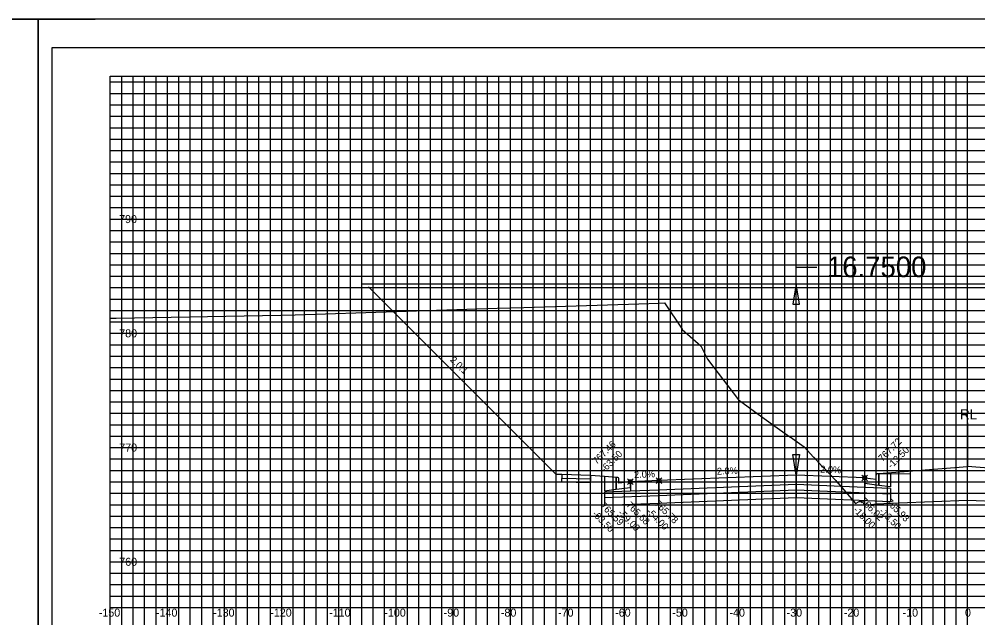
# Model space of a CAD drawing. Extents: x 578243 to 601557, y 174899 to 175559.
# Drawn here: x 600533.9 to 600701.6, y 175014 to 175118.8 of the extents above; entities that cross this region are included whole.
import ezdxf

# ---------------------------------------------------------------- set-up
doc = ezdxf.new("R2010")
doc.units = 0
for name, color, linetype in [('E_PROF_Grid', 7, 'Continuous'), ('E_PROF_GridMin', 7, 'Continuous'), ('P_CRDR_Label', 7, 'Continuous'), ('P_CRDR_Link', 7, 'Continuous'), ('P_E_XS_Ground', 7, 'Continuous'), ('P_RW_SlopeIntercepts', 7, 'Continuous'), ('P_XS_Text', 7, 'Continuous'), ('PLT_Sheet_Border', 7, 'Continuous'), ('PLT_Sheet_Info', 7, 'Continuous')]:
    doc.layers.add(name, color=color, linetype=linetype)

msp = doc.modelspace()

# ---------------------------------------------------------------- linework, layer by layer
at = {"layer": 'E_PROF_Grid'}
for p, q in [((600559.84, 174913.8), (600559.84, 175108.8)), ((600569.84, 174913.8), (600569.84, 175108.8)), ((600579.84, 174913.8), (600579.84, 175108.8)), ((600589.84, 174913.8), (600589.84, 175108.8)), ((600599.84, 174913.8), (600599.84, 175108.8)), ((600609.84, 174913.8), (600609.84, 175108.8)), ((600619.84, 174913.8), (600619.84, 175108.8)), ((600629.84, 174913.8), (600629.84, 175108.8)), ((600639.84, 174913.8), (600639.84, 175108.8)), ((600649.84, 174913.8), (600649.84, 175108.8)), ((600659.84, 174913.8), (600659.84, 175108.8)), ((600669.84, 174913.8), (600669.84, 175108.8)), ((600679.84, 174913.8), (600679.84, 175108.8)), ((600689.84, 174913.8), (600689.84, 175108.8)), ((600699.84, 174913.8), (600699.84, 175108.8)), ((600549.84, 175103.8), (600864.84, 175103.8)), ((600549.84, 175093.8), (600864.84, 175093.8)), ((600549.84, 175083.8), (600864.84, 175083.8)), ((600549.84, 175073.8), (600864.84, 175073.8)), ((600549.84, 175063.8), (600864.84, 175063.8)), ((600549.84, 175053.8), (600864.84, 175053.8)), ((600549.84, 175043.8), (600864.84, 175043.8)), ((600549.84, 175033.8), (600864.84, 175033.8)), ((600549.84, 175023.8), (600864.84, 175023.8))]:
    msp.add_line(p, q, dxfattribs=at)
at = {"layer": 'E_PROF_GridMin'}
for p, q in [((600551.84, 174913.8), (600551.84, 175108.8)), ((600553.84, 174913.8), (600553.84, 175108.8)), ((600555.84, 174913.8), (600555.84, 175108.8)), ((600557.84, 174913.8), (600557.84, 175108.8)), ((600561.84, 174913.8), (600561.84, 175108.8)), ((600563.84, 174913.8), (600563.84, 175108.8)), ((600565.84, 174913.8), (600565.84, 175108.8)), ((600567.84, 174913.8), (600567.84, 175108.8)), ((600571.84, 174913.8), (600571.84, 175108.8)), ((600573.84, 174913.8), (600573.84, 175108.8)), ((600575.84, 174913.8), (600575.84, 175108.8)), ((600577.84, 174913.8), (600577.84, 175108.8)), ((600581.84, 174913.8), (600581.84, 175108.8)), ((600583.84, 174913.8), (600583.84, 175108.8)), ((600585.84, 174913.8), (600585.84, 175108.8)), ((600587.84, 174913.8), (600587.84, 175108.8)), ((600591.84, 174913.8), (600591.84, 175108.8)), ((600593.84, 174913.8), (600593.84, 175108.8)), ((600595.84, 174913.8), (600595.84, 175108.8)), ((600597.84, 174913.8), (600597.84, 175108.8)), ((600601.84, 174913.8), (600601.84, 175108.8)), ((600603.84, 174913.8), (600603.84, 175108.8)), ((600605.84, 174913.8), (600605.84, 175108.8)), ((600607.84, 174913.8), (600607.84, 175108.8)), ((600611.84, 174913.8), (600611.84, 175108.8)), ((600613.84, 174913.8), (600613.84, 175108.8)), ((600615.84, 174913.8), (600615.84, 175108.8)), ((600617.84, 174913.8), (600617.84, 175108.8)), ((600621.84, 174913.8), (600621.84, 175108.8)), ((600623.84, 174913.8), (600623.84, 175108.8)), ((600625.84, 174913.8), (600625.84, 175108.8)), ((600627.84, 174913.8), (600627.84, 175108.8)), ((600631.84, 174913.8), (600631.84, 175108.8)), ((600633.84, 174913.8), (600633.84, 175108.8)), ((600635.84, 174913.8), (600635.84, 175108.8)), ((600637.84, 174913.8), (600637.84, 175108.8)), ((600641.84, 174913.8), (600641.84, 175108.8)), ((600643.84, 174913.8), (600643.84, 175108.8)), ((600645.84, 174913.8), (600645.84, 175108.8)), ((600647.84, 174913.8), (600647.84, 175108.8)), ((600651.84, 174913.8), (600651.84, 175108.8)), ((600653.84, 174913.8), (600653.84, 175108.8)), ((600655.84, 174913.8), (600655.84, 175108.8)), ((600657.84, 174913.8), (600657.84, 175108.8)), ((600661.84, 174913.8), (600661.84, 175108.8)), ((600663.84, 174913.8), (600663.84, 175108.8)), ((600665.84, 174913.8), (600665.84, 175108.8)), ((600667.84, 174913.8), (600667.84, 175108.8)), ((600671.84, 174913.8), (600671.84, 175108.8)), ((600673.84, 174913.8), (600673.84, 175108.8)), ((600675.84, 174913.8), (600675.84, 175108.8)), ((600677.84, 174913.8), (600677.84, 175108.8)), ((600681.84, 174913.8), (600681.84, 175108.8)), ((600683.84, 174913.8), (600683.84, 175108.8)), ((600685.84, 174913.8), (600685.84, 175108.8)), ((600687.84, 174913.8), (600687.84, 175108.8)), ((600691.84, 174913.8), (600691.84, 175108.8)), ((600693.84, 174913.8), (600693.84, 175108.8)), ((600695.84, 174913.8), (600695.84, 175108.8)), ((600697.84, 174913.8), (600697.84, 175108.8)), ((600549.84, 175107.8), (600864.84, 175107.8)), ((600549.84, 175105.8), (600864.84, 175105.8)), ((600549.84, 175101.8), (600864.84, 175101.8)), ((600549.84, 175099.8), (600864.84, 175099.8)), ((600549.84, 175097.8), (600864.84, 175097.8)), ((600549.84, 175095.8), (600864.84, 175095.8)), ((600549.84, 175091.8), (600864.84, 175091.8)), ((600549.84, 175089.8), (600864.84, 175089.8)), ((600549.84, 175087.8), (600864.84, 175087.8)), ((600549.84, 175085.8), (600864.84, 175085.8)), ((600549.84, 175081.8), (600864.84, 175081.8)), ((600549.84, 175079.8), (600864.84, 175079.8)), ((600549.84, 175077.8), (600864.84, 175077.8)), ((600549.84, 175075.8), (600864.84, 175075.8)), ((600549.84, 175071.8), (600864.84, 175071.8)), ((600549.84, 175069.8), (600864.84, 175069.8)), ((600549.84, 175067.8), (600864.84, 175067.8)), ((600549.84, 175065.8), (600864.84, 175065.8)), ((600549.84, 175061.8), (600864.84, 175061.8)), ((600549.84, 175059.8), (600864.84, 175059.8)), ((600549.84, 175057.8), (600864.84, 175057.8)), ((600549.84, 175055.8), (600864.84, 175055.8)), ((600549.84, 175051.8), (600864.84, 175051.8)), ((600549.84, 175049.8), (600864.84, 175049.8)), ((600549.84, 175047.8), (600864.84, 175047.8)), ((600549.84, 175045.8), (600864.84, 175045.8)), ((600549.84, 175041.8), (600864.84, 175041.8)), ((600549.84, 175039.8), (600864.84, 175039.8)), ((600549.84, 175037.8), (600864.84, 175037.8)), ((600549.84, 175035.8), (600864.84, 175035.8)), ((600549.84, 175031.8), (600864.84, 175031.8)), ((600549.84, 175029.8), (600864.84, 175029.8)), ((600549.84, 175027.8), (600864.84, 175027.8)), ((600549.84, 175025.8), (600864.84, 175025.8)), ((600549.84, 175021.8), (600864.84, 175021.8)), ((600549.84, 175019.8), (600864.84, 175019.8)), ((600549.84, 175017.8), (600864.84, 175017.8)), ((600549.84, 175015.8), (600864.84, 175015.8))]:
    msp.add_line(p, q, dxfattribs=at)
at = {"layer": 'P_CRDR_Label'}
for points in [[(600699.84, 175048.11), (600699.84, 175040.49)], [(600640.35, 175037.32), (600641.34, 175038.31)], [(600640.35, 175038.31), (600641.34, 175037.32)], [(600645.35, 175037.52), (600646.34, 175038.51)], [(600645.35, 175038.51), (600646.34, 175037.52)], [(600681.35, 175038), (600682.34, 175038.99)], [(600681.35, 175038.99), (600682.34, 175038)]]:
    msp.add_lwpolyline(points, dxfattribs=at)
for centre in [(600640.84, 175037.82), (600645.84, 175038.02), (600681.84, 175038.5)]:
    msp.add_circle(centre, 0.35, dxfattribs=at)
at = {"layer": 'P_CRDR_Link'}
msp.add_line((600594.99, 175071.96), (600627.84, 175039.11), dxfattribs=at)
for points in [[(600684.34, 175039.25), (600699.84, 175040.49)], [(600684.34, 175039.25), (600699.84, 175040.49)], [(600715.34, 175039.25), (600699.84, 175040.49)], [(600715.34, 175039.25), (600699.84, 175040.49)], [(600628.84, 175039.08), (600627.84, 175039.11)], [(600628.84, 175039.08), (600627.84, 175039.11)], [(600633.84, 175038.93), (600628.84, 175039.08)], [(600633.84, 175038.93), (600628.84, 175039.08)], [(600628.84, 175039.08), (600628.85, 175038.41)], [(600633.84, 175038.26), (600628.85, 175038.41)], [(600628.85, 175037.75), (600628.85, 175038.41)], [(600633.83, 175037.6), (600628.85, 175037.75)], [(600633.84, 175038.26), (600633.83, 175037.6)], [(600636.34, 175038.73), (600633.84, 175038.93)], [(600636.34, 175038.73), (600633.84, 175038.93)], [(600633.84, 175038.93), (600633.84, 175038.26)], [(600638.34, 175038.57), (600636.34, 175038.73)], [(600636.34, 175038.73), (600636.34, 175036.25)], [(600636.34, 175038.73), (600636.34, 175036.25)], [(600636.34, 175038.73), (600636.34, 175036.25)], [(600638.66, 175038.57), (600638.34, 175038.57)], [(600638.66, 175038.57), (600638.34, 175038.57)], [(600638.34, 175038.57), (600638.34, 175036.5)], [(600638.34, 175036.5), (600638.34, 175038.57)], [(600638.74, 175038.52), (600638.66, 175038.57)], [(600638.74, 175038.52), (600638.66, 175038.57)], [(600638.8, 175038.41), (600638.74, 175038.52)], [(600638.8, 175038.41), (600638.74, 175038.52)], [(600638.83, 175038.25), (600638.8, 175038.41)], [(600638.83, 175038.25), (600638.8, 175038.41)], [(600638.84, 175037.57), (600638.83, 175038.25)], [(600638.84, 175037.57), (600638.83, 175038.25)], [(600640.84, 175037.82), (600638.84, 175037.57)], [(600640.84, 175037.82), (600638.84, 175037.57)], [(600645.84, 175038.02), (600640.84, 175037.82)], [(600640.84, 175037.82), (600640.84, 175036.15)], [(600640.84, 175036.82), (600640.84, 175037.82)], [(600669.84, 175038.98), (600645.84, 175038.02)], [(600645.84, 175038.02), (600645.84, 175036.35)], [(600645.84, 175038.02), (600645.84, 175036.35)], [(600681.84, 175038.5), (600669.84, 175038.98)], [(600669.84, 175038.98), (600669.84, 175037.31)], [(600669.84, 175038.98), (600669.84, 175037.31)], [(600681.84, 175038.5), (600683.84, 175038.25)], [(600681.84, 175038.5), (600683.84, 175038.25)], [(600681.84, 175037.5), (600681.84, 175038.5)], [(600681.84, 175038.5), (600681.84, 175036.83)], [(600683.84, 175038.25), (600683.85, 175038.93)], [(600683.84, 175038.25), (600683.85, 175038.93)], [(600683.85, 175038.93), (600683.88, 175039.09)], [(600683.85, 175038.93), (600683.88, 175039.09)], [(600683.88, 175039.09), (600683.94, 175039.2)], [(600683.88, 175039.09), (600683.94, 175039.2)], [(600683.94, 175039.2), (600684.02, 175039.25)], [(600683.94, 175039.2), (600684.02, 175039.25)], [(600684.02, 175039.25), (600684.34, 175039.25)], [(600684.02, 175039.25), (600684.34, 175039.25)], [(600684.34, 175039.25), (600684.34, 175037.18)], [(600684.34, 175039.25), (600686.34, 175039.23)], [(600684.34, 175037.18), (600684.34, 175039.25)], [(600686.34, 175039.23), (600686.34, 175036.93)], [(600686.34, 175039.23), (600686.34, 175036.93)], [(600686.34, 175039.23), (600686.34, 175036.93)], [(600686.34, 175039.23), (600689.84, 175039.2)], [(600686.34, 175039.23), (600689.84, 175039.2)], [(600636.34, 175036.25), (600638.34, 175036.5)], [(600640.84, 175036.15), (600636.34, 175035.97)], [(600638.34, 175036.5), (600640.84, 175036.82)], [(600638.34, 175036.5), (600640.84, 175036.82)], [(600645.84, 175036.35), (600640.84, 175036.15)], [(600669.84, 175037.31), (600645.84, 175036.35)], [(600645.84, 175036.35), (600645.84, 175035.35)], [(600645.84, 175036.35), (600645.84, 175035.35)], [(600669.84, 175036.31), (600645.84, 175035.35)], [(600681.84, 175036.83), (600669.84, 175037.31)], [(600669.84, 175037.31), (600669.84, 175036.31)], [(600669.84, 175037.31), (600669.84, 175036.31)], [(600686.34, 175035.65), (600669.84, 175036.31)], [(600669.84, 175036.31), (600669.84, 175034.98)], [(600669.84, 175036.31), (600669.84, 175034.98)], [(600684.34, 175037.18), (600681.84, 175037.5)], [(600684.34, 175037.18), (600681.84, 175037.5)], [(600686.34, 175036.65), (600681.84, 175036.83)], [(600686.34, 175036.93), (600684.34, 175037.18)], [(600686.34, 175036.65), (600686.34, 175035.65)], [(600636.34, 175035.97), (600636.34, 175034.97)], [(600645.84, 175035.35), (600636.34, 175034.97)], [(600636.34, 175034.97), (600636.34, 175033.64)], [(600645.84, 175035.35), (600645.84, 175034.02)], [(600645.84, 175035.35), (600645.84, 175034.02)], [(600669.84, 175034.98), (600645.84, 175034.02)], [(600686.34, 175034.32), (600669.84, 175034.98)], [(600686.34, 175035.65), (600686.34, 175034.32)], [(600645.84, 175034.02), (600636.34, 175033.64)]]:
    msp.add_lwpolyline(points, dxfattribs=at)
at = {"layer": 'P_E_XS_Ground'}
msp.add_lwpolyline([(600549.84, 175066.46), (600550.85, 175066.47), (600579.7, 175066.99), (600582.16, 175067.06), (600617.55, 175068.21), (600622.19, 175068.31), (600642.29, 175068.97), (600645.87, 175069.1), (600646.83, 175069.11), (600649.88, 175064.53), (600649.93, 175064.47), (600653.14, 175061.61), (600654.36, 175059.25), (600659.78, 175052.14), (600660.55, 175051.58), (600662.56, 175050.11), (600665.72, 175047.86), (600668.75, 175045.69), (600668.78, 175045.66), (600671.22, 175043.92), (600672.91, 175042.11), (600672.92, 175042.09), (600673.87, 175041.05), (600674.46, 175040.43), (600674.6, 175040.31), (600674.61, 175040.31), (600676.8, 175038.06), (600677.11, 175037.64), (600677.12, 175037.64), (600680.25, 175034.01), (600680.9, 175034.38), (600680.9, 175034.38), (600681.32, 175034.38), (600681.9, 175033.72), (600683.9, 175033.97), (600687.84, 175034.12), (600699.84, 175034.6), (600711.84, 175034.12)], dxfattribs=at)
at = {"layer": 'P_RW_SlopeIntercepts'}
for p, q in [((600669.84, 175075.4), (600673.44, 175075.4)), ((600669.84, 175038.98), (600669.84, 175075.4)), ((600593.84, 175072.48), (600829.84, 175072.48)), ((600669.84, 175072.48), (600669.24, 175068.88)), ((600670.44, 175068.88), (600669.84, 175072.48)), ((600669.24, 175068.88), (600670.44, 175068.88)), ((600669.24, 175042.58), (600670.44, 175042.58)), ((600669.84, 175038.98), (600669.24, 175042.58)), ((600670.44, 175042.58), (600669.84, 175038.98))]:
    msp.add_line(p, q, dxfattribs=at)
at = {"layer": 'PLT_Sheet_Border'}
for points in [[(600197.19, 174898.8), (600537.19, 174898.8), (600537.19, 175118.8), (600197.19, 175118.8)], [(600537.19, 174898.8), (600877.19, 174898.8), (600877.19, 175118.8), (600537.19, 175118.8)], [(600539.59, 174903.8), (600870.59, 174903.8), (600870.59, 175113.8), (600539.59, 175113.8)]]:
    msp.add_lwpolyline(points, close=True, dxfattribs=at)
at = {"layer": 'PLT_Sheet_Info'}
for p, q in [((600527.19, 175118.8), (600537.19, 175118.8)), ((600537.19, 175108.8), (600537.19, 175118.8)), ((600537.19, 175108.8), (600537.19, 175118.8)), ((600537.19, 175118.8), (600547.19, 175118.8)), ((600549.84, 175108.8), (600864.84, 175108.8)), ((600549.84, 174908.8), (600549.84, 175108.8))]:
    msp.add_line(p, q, dxfattribs=at)

# ---------------------------------------------------------------- texts
at = {"layer": 'P_CRDR_Label'}
for s, rotation, p in [('2.0:1', 315.8532, (600609.19, 175059.04)), ('767.46', 45, (600634.93, 175040.77)), ('767.72', 45, (600684.93, 175041.27)), ('-63.50', 45, (600636.34, 175039.36)), ('-13.50', 45, (600686.52, 175040.04)), ('2.0%', 2.2906, (600641.5, 175038.46)), ('2.0%', 2.2906, (600656, 175039.04)), ('2.0%', 357.7094, (600674.05, 175039.43)), ('765.68', 315, (600640.03, 175033.64)), ('765.78', 315, (600645.02, 175033.84)), ('766.02', 315, (600680.99, 175034.35)), ('765.93', 315, (600685.49, 175034.17)), ('765.59', 315, (600635.49, 175033.49)), ('-54.00', 315, (600643.58, 175032.46)), ('-18.00', 315, (600679.76, 175032.76)), ('-13.50', 315, (600684.26, 175032.58)), ('-63.50', 315, (600634.08, 175032.08)), ('-59.00', 315, (600638.58, 175032.26))]:
    msp.add_text(s, height=1.2, rotation=rotation, dxfattribs=at).set_placement(p)
msp.add_text('RL', height=1.75, dxfattribs=at).set_placement((600698.52, 175048.74))
at = {"layer": 'P_RW_SlopeIntercepts'}
msp.add_text('16.7500', height=3.6, dxfattribs=at).set_placement((600675.24, 175073.63))
at = {"layer": 'P_XS_Text'}
for s, p in [('790', (600551.38, 175083.1)), ('780', (600551.4, 175063.1)), ('770', (600551.4, 175043.1)), ('760', (600551.4, 175023.1)), ('-150', (600547.83, 175014.2)), ('-140', (600557.83, 175014.2)), ('-130', (600567.83, 175014.2)), ('-120', (600577.83, 175014.2)), ('-110', (600588.13, 175014.2)), ('-100', (600597.79, 175014.2)), ('-90', (600608.17, 175014.2)), ('-80', (600618.18, 175014.2)), ('-70', (600628.18, 175014.2)), ('-60', (600638.18, 175014.2)), ('-50', (600648.18, 175014.2)), ('-40', (600658.18, 175014.2)), ('-30', (600668.18, 175014.2)), ('-20', (600678.18, 175014.2)), ('-10', (600688.47, 175014.2)), ('0', (600699.39, 175014.2)), ('0', (600699.39, 175014.2))]:
    msp.add_text(s, height=1.4, rotation=360, dxfattribs=at).set_placement(p)

doc.saveas('drawing.dxf')
